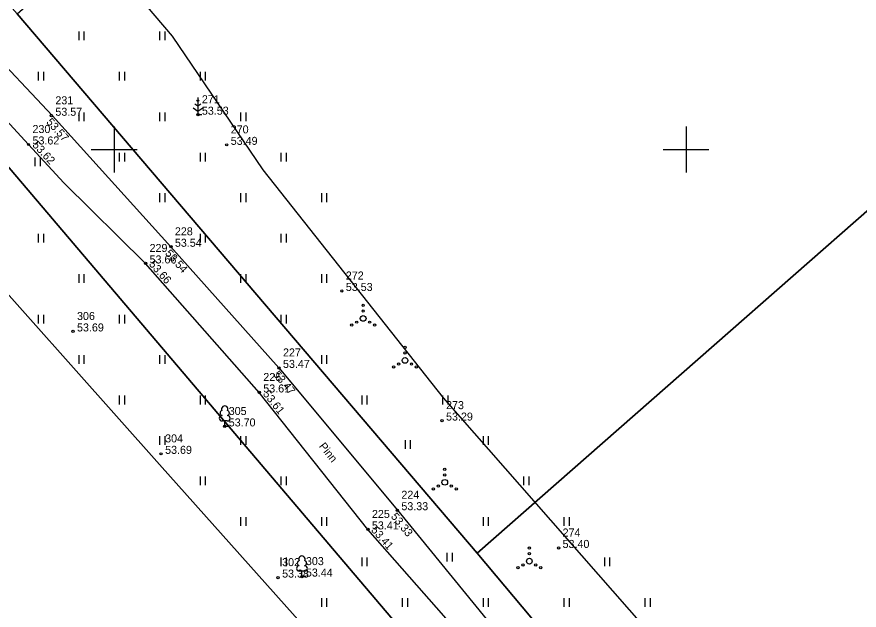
# Model space of a CAD drawing. Extents: x 538599 to 541973, y 6559689 to 6564516.
# Drawn here: x 540391.5 to 540465.1, y 6561409.8 to 6561461.6 of the extents above; entities that cross this region are included whole.
import ezdxf

# ---------------------------------------------------------------- set-up
doc = ezdxf.new("R2010")
doc.units = 0
for name, color, linetype in [('HALJASTUS', 7, 'Continuous'), ('KORGUS-EH2000', 7, 'Continuous'), ('MOOTKORG-EH2000', 7, 'Continuous'), ('MOOTMPUNKT', 7, 'Continuous'), ('MOOTNR', 7, 'Continuous'), ('MOOTPIIR', 7, 'Continuous'), ('PIIR', 7, 'Continuous'), ('PUU', 7, 'Continuous'), ('TEE', 7, 'Continuous'), ('VORK', 7, 'Continuous')]:
    doc.layers.add(name, color=color, linetype=linetype)

msp = doc.modelspace()

# ---------------------------------------------------------------- linework, layer by layer
at = {"layer": 'HALJASTUS'}
for p, q in [((540396.9, 6561460.313), (540396.9, 6561459.552)), ((540397.355, 6561460.313), (540397.355, 6561459.552)), ((540403.971, 6561460.313), (540403.971, 6561459.552)), ((540404.426, 6561460.313), (540404.426, 6561459.552)), ((540393.364, 6561456.777), (540393.364, 6561456.016)), ((540393.819, 6561456.777), (540393.819, 6561456.016)), ((540400.435, 6561456.777), (540400.435, 6561456.016)), ((540400.89, 6561456.777), (540400.89, 6561456.016)), ((540407.506, 6561456.777), (540407.506, 6561456.016)), ((540407.961, 6561456.777), (540407.961, 6561456.016)), ((540396.9, 6561453.242), (540396.9, 6561452.48)), ((540397.355, 6561453.242), (540397.355, 6561452.48)), ((540403.971, 6561453.242), (540403.971, 6561452.48)), ((540404.426, 6561453.242), (540404.426, 6561452.48)), ((540411.042, 6561453.242), (540411.042, 6561452.48)), ((540411.497, 6561453.242), (540411.497, 6561452.48)), ((540393.061, 6561449.311), (540393.061, 6561448.55)), ((540393.516, 6561449.311), (540393.516, 6561448.55)), ((540400.435, 6561449.706), (540400.435, 6561448.945)), ((540400.89, 6561449.706), (540400.89, 6561448.945)), ((540407.506, 6561449.706), (540407.506, 6561448.945)), ((540407.961, 6561449.706), (540407.961, 6561448.945)), ((540414.577, 6561449.706), (540414.577, 6561448.945)), ((540415.032, 6561449.706), (540415.032, 6561448.945)), ((540403.971, 6561446.171), (540403.971, 6561445.409)), ((540404.426, 6561446.171), (540404.426, 6561445.409)), ((540411.042, 6561446.171), (540411.042, 6561445.409)), ((540411.497, 6561446.171), (540411.497, 6561445.409)), ((540418.113, 6561446.171), (540418.113, 6561445.409)), ((540418.568, 6561446.171), (540418.568, 6561445.409)), ((540393.364, 6561442.635), (540393.364, 6561441.874)), ((540393.819, 6561442.635), (540393.819, 6561441.874)), ((540407.506, 6561442.635), (540407.506, 6561441.874)), ((540407.961, 6561442.635), (540407.961, 6561441.874)), ((540414.577, 6561442.635), (540414.577, 6561441.874)), ((540415.032, 6561442.635), (540415.032, 6561441.874)), ((540396.9, 6561439.099), (540396.9, 6561438.338)), ((540397.355, 6561439.099), (540397.355, 6561438.338)), ((540411.042, 6561439.099), (540411.042, 6561438.338)), ((540411.497, 6561439.099), (540411.497, 6561438.338)), ((540418.113, 6561439.099), (540418.113, 6561438.338)), ((540418.568, 6561439.099), (540418.568, 6561438.338)), ((540393.364, 6561435.564), (540393.364, 6561434.803)), ((540393.819, 6561435.564), (540393.819, 6561434.803)), ((540400.435, 6561435.564), (540400.435, 6561434.803)), ((540400.89, 6561435.564), (540400.89, 6561434.803)), ((540414.577, 6561435.564), (540414.577, 6561434.803)), ((540415.032, 6561435.564), (540415.032, 6561434.803)), ((540396.9, 6561432.028), (540396.9, 6561431.267)), ((540397.355, 6561432.028), (540397.355, 6561431.267)), ((540403.971, 6561432.028), (540403.971, 6561431.267)), ((540404.426, 6561432.028), (540404.426, 6561431.267)), ((540418.113, 6561432.028), (540418.113, 6561431.267)), ((540418.568, 6561432.028), (540418.568, 6561431.267)), ((540400.435, 6561428.493), (540400.435, 6561427.732)), ((540400.89, 6561428.493), (540400.89, 6561427.732)), ((540407.506, 6561428.493), (540407.506, 6561427.732)), ((540407.961, 6561428.493), (540407.961, 6561427.732)), ((540421.648, 6561428.493), (540421.648, 6561427.732)), ((540422.103, 6561428.493), (540422.103, 6561427.732)), ((540428.719, 6561428.493), (540428.719, 6561427.732)), ((540429.175, 6561428.493), (540429.175, 6561427.732)), ((540403.971, 6561424.957), (540403.971, 6561424.196)), ((540404.426, 6561424.957), (540404.426, 6561424.196)), ((540411.042, 6561424.957), (540411.042, 6561424.196)), ((540411.497, 6561424.957), (540411.497, 6561424.196)), ((540432.255, 6561424.957), (540432.255, 6561424.196)), ((540432.71, 6561424.957), (540432.71, 6561424.196)), ((540425.436, 6561424.598), (540425.436, 6561423.836)), ((540425.891, 6561424.598), (540425.891, 6561423.836)), ((540407.506, 6561421.422), (540407.506, 6561420.661)), ((540407.961, 6561421.422), (540407.961, 6561420.661)), ((540414.577, 6561421.422), (540414.577, 6561420.661)), ((540415.032, 6561421.422), (540415.032, 6561420.661)), ((540435.791, 6561421.422), (540435.791, 6561420.661)), ((540436.246, 6561421.422), (540436.246, 6561420.661)), ((540411.042, 6561417.886), (540411.042, 6561417.125)), ((540411.497, 6561417.886), (540411.497, 6561417.125)), ((540418.113, 6561417.886), (540418.113, 6561417.125)), ((540418.568, 6561417.886), (540418.568, 6561417.125)), ((540432.255, 6561417.886), (540432.255, 6561417.125)), ((540432.71, 6561417.886), (540432.71, 6561417.125)), ((540439.326, 6561417.886), (540439.326, 6561417.125)), ((540439.781, 6561417.886), (540439.781, 6561417.125)), ((540429.096, 6561414.775), (540429.096, 6561414.014)), ((540429.551, 6561414.775), (540429.551, 6561414.014)), ((540414.577, 6561414.351), (540414.577, 6561413.59)), ((540415.032, 6561414.351), (540415.032, 6561413.59)), ((540421.648, 6561414.351), (540421.648, 6561413.59)), ((540422.103, 6561414.351), (540422.103, 6561413.59)), ((540442.862, 6561414.351), (540442.862, 6561413.59)), ((540443.317, 6561414.351), (540443.317, 6561413.59)), ((540418.113, 6561410.815), (540418.113, 6561410.054)), ((540418.568, 6561410.815), (540418.568, 6561410.054)), ((540425.184, 6561410.815), (540425.184, 6561410.054)), ((540425.639, 6561410.815), (540425.639, 6561410.054)), ((540432.255, 6561410.815), (540432.255, 6561410.054)), ((540432.71, 6561410.815), (540432.71, 6561410.054)), ((540439.326, 6561410.815), (540439.326, 6561410.054)), ((540439.781, 6561410.815), (540439.781, 6561410.054)), ((540446.397, 6561410.815), (540446.397, 6561410.054)), ((540446.852, 6561410.815), (540446.852, 6561410.054))]:
    msp.add_line(p, q, dxfattribs=at)
for centre, radius in [((540421.77, 6561436.387), 0.1), ((540421.77, 6561435.887), 0.1), ((540421.77, 6561435.237), 0.25), ((540420.77, 6561434.662), 0.1), ((540421.205, 6561434.912), 0.1), ((540422.335, 6561434.912), 0.1), ((540422.77, 6561434.662), 0.1), ((540425.43, 6561432.726), 0.1), ((540425.43, 6561432.226), 0.1), ((540425.43, 6561431.576), 0.25), ((540424.43, 6561431.001), 0.1), ((540424.865, 6561431.251), 0.1), ((540425.995, 6561431.251), 0.1), ((540426.43, 6561431.001), 0.1), ((540428.908, 6561422.07), 0.1), ((540428.908, 6561420.92), 0.25), ((540428.908, 6561421.57), 0.1), ((540427.908, 6561420.345), 0.1), ((540428.343, 6561420.595), 0.1), ((540429.473, 6561420.595), 0.1), ((540429.908, 6561420.345), 0.1), ((540436.3, 6561415.183), 0.1), ((540436.3, 6561414.683), 0.1), ((540435.735, 6561413.708), 0.1), ((540436.3, 6561414.033), 0.25), ((540436.865, 6561413.708), 0.1), ((540435.3, 6561413.458), 0.1), ((540437.3, 6561413.458), 0.1)]:
    msp.add_circle(centre, radius, dxfattribs=at)
at = {"layer": 'KORGUS-EH2000'}
for centre in [(540394.506, 6561452.944), (540392.506, 6561450.435), (540409.841, 6561450.403), (540404.957, 6561441.5), (540402.743, 6561440.044), (540419.903, 6561437.639), (540396.4, 6561434.103), (540414.409, 6561430.917), (540412.686, 6561428.773), (540428.668, 6561426.316), (540404.103, 6561423.41), (540424.761, 6561418.487), (540422.187, 6561416.809), (540438.858, 6561415.19), (540414.334, 6561412.601)]:
    msp.add_circle(centre, 0.1, dxfattribs=at)
at = {"layer": 'MOOTMPUNKT'}
for centre in [(540394.506, 6561452.944), (540407.317, 6561453.036), (540392.506, 6561450.435), (540409.841, 6561450.403), (540404.957, 6561441.5), (540402.743, 6561440.044), (540419.903, 6561437.639), (540396.4, 6561434.103), (540414.409, 6561430.917), (540412.686, 6561428.773), (540428.668, 6561426.316), (540409.666, 6561425.805), (540404.103, 6561423.41), (540424.761, 6561418.487), (540422.187, 6561416.809), (540438.858, 6561415.19), (540414.334, 6561412.601), (540416.414, 6561412.691)]:
    msp.add_circle(centre, 0.1, dxfattribs=at)
at = {"layer": 'MOOTPIIR'}
for points in [[(540611.814, 6561347.628), (540600.551, 6561344.045), (540588.991, 6561338.307), (540579.507, 6561329.749), (540567.369, 6561324.711), (540557.296, 6561315.504), (540537.549, 6561303.29), (540525.23, 6561316.048), (540500.22, 6561345.282), (540476.488, 6561371.995), (540449.028, 6561405.277), (540428.792, 6561428.292), (540413.022, 6561448.218), (540405.096, 6561459.889), (540393.809, 6561473.145)], [(540384.887, 6561443.845), (540403.973, 6561422.469), (540424.304, 6561399.698), (540444.636, 6561376.927), (540453.177, 6561363.987), (540470.995, 6561343.689), (540492.689, 6561318.976), (540511.766, 6561294.341), (540521.974, 6561279.181), (540525.589, 6561267.954), (540536.495, 6561252.794), (540542.772, 6561231.926), (540526.603, 6561219.05), (540510.624, 6561213.468), (540498.26, 6561199.196), (540484.564, 6561192.98), (540479.618, 6561185.622), (540478.413, 6561178.328), (540490.461, 6561165.832), (540493.58, 6561162.597), (540531.105, 6561187.906), (540582.869, 6561222.817), (540621.742, 6561247.747)]]:
    msp.add_lwpolyline(points, dxfattribs=at)
at = {"layer": 'PIIR'}
for points in [[(540491.21, 6561183.5), (540566.07, 6561233.36), (540528.84, 6561281.85), (540494.34, 6561324.62), (540458.27, 6561368.69), (540424.68, 6561408.57), (540384.55, 6561455.73), (540346.17, 6561499.11), (540330.12, 6561517.14), (540337.36, 6561523.32), (540348.28, 6561532.96), (540364.11, 6561514.94), (540353.14, 6561505.27), (540391.51, 6561461.86), (540431.74, 6561414.74), (540465.17, 6561374.89), (540501.31, 6561330.86), (540535.92, 6561287.97), (540573.77, 6561238.75), (540640.63, 6561283.66), (540646.74, 6561272.89), (540499, 6561174.36)], [(540391.51, 6561461.86), (540460.86, 6561522.64), (540500.82, 6561475.34), (540431.74, 6561414.74)], [(540431.74, 6561414.74), (540500.82, 6561475.34), (540537.11, 6561431.06), (540465.17, 6561374.89)], [(540309.49, 6561390.29), (540384.55, 6561455.73), (540424.68, 6561408.57), (540350.66, 6561343.77)]]:
    msp.add_lwpolyline(points, close=True, dxfattribs=at)
at = {"layer": 'PUU'}
for p, q in [((540407.317, 6561454.186), (540407.193, 6561454.269)), ((540407.317, 6561454.536), (540407.317, 6561453.036)), ((540407.441, 6561454.269), (540407.317, 6561454.186)), ((540406.893, 6561453.625), (540407.317, 6561453.343)), ((540407.317, 6561453.786), (540407.05, 6561453.964)), ((540407.584, 6561453.964), (540407.317, 6561453.786)), ((540407.317, 6561453.343), (540407.741, 6561453.625)), ((540407.677, 6561453.036), (540407.317, 6561453.036)), ((540409.906, 6561426.28), (540409.426, 6561426.28)), ((540409.666, 6561425.805), (540409.666, 6561426.28)), ((540410.046, 6561425.805), (540409.666, 6561425.805)), ((540416.654, 6561413.166), (540416.174, 6561413.166)), ((540416.414, 6561412.691), (540416.414, 6561413.166)), ((540416.794, 6561412.691), (540416.414, 6561412.691))]:
    msp.add_line(p, q, dxfattribs=at)
for centre, radius, start, end in [((540409.496, 6561426.978), 0.233, 109.02174, 253.14154), ((540409.666, 6561427.325), 0.277, 332.5799, 207.4201), ((540409.836, 6561426.978), 0.233, 286.85082, 70.98591), ((540409.429, 6561426.517), 0.238, 90.0016, 269.3953), ((540409.903, 6561426.517), 0.238, 270.6047, 89.9984), ((540416.414, 6561414.211), 0.277, 332.5799, 207.4201), ((540416.244, 6561413.864), 0.233, 109.02174, 253.14154), ((540416.584, 6561413.864), 0.233, 286.85082, 70.98591), ((540416.177, 6561413.403), 0.238, 90.0016, 269.3953), ((540416.651, 6561413.403), 0.238, 270.6047, 89.9984)]:
    msp.add_arc(centre, radius, start, end, dxfattribs=at)
at = {"layer": 'TEE'}
for points in [[(540488.154, 6561336.579), (540478.587, 6561348.431), (540467.854, 6561361.491), (540459.324, 6561371.761), (540451.227, 6561381.751), (540441.058, 6561393.627), (540438.742, 6561396.541), (540432.536, 6561404.858), (540428.826, 6561409.256), (540422.187, 6561416.809), (540412.686, 6561428.773), (540402.743, 6561440.044), (540395.606, 6561447.094), (540392.506, 6561450.435), (540382.51, 6561461.307)], [(540388.6, 6561459.282), (540394.606, 6561452.944), (540404.957, 6561441.5), (540414.409, 6561430.917), (540424.761, 6561418.487), (540434.319, 6561406.773), (540435.946, 6561404.714), (540443.752, 6561395.534), (540453.227, 6561383.82), (540461.243, 6561373.674), (540469.957, 6561362.956), (540476.197, 6561354.987), (540480.237, 6561350.173), (540490.343, 6561338.333)]]:
    msp.add_lwpolyline(points, dxfattribs=at)
at = {"layer": 'VORK'}
for p, q in [((540400, 6561452), (540400, 6561448)), ((540450, 6561452), (540450, 6561448)), ((540398, 6561450), (540402, 6561450)), ((540448, 6561450), (540452, 6561450))]:
    msp.add_line(p, q, dxfattribs=at)

# ---------------------------------------------------------------- texts
at = {"layer": 'KORGUS-EH2000'}
for s, rotation, p in [('53.57', 312.12907, (540394.01, 6561452.357)), ('53.62', 312.84976, (540392.798, 6561450.346)), ('53.54', 311.76901, (540404.403, 6561440.886)), ('53.66', 311.41795, (540402.993, 6561439.947)), ('53.47', 309.78834, (540413.867, 6561430.308)), ('53.61', 308.45423, (540412.962, 6561428.624)), ('53.33', 309.21261, (540424.151, 6561417.919)), ('53.41', 311.31429, (540422.415, 6561416.721))]:
    msp.add_text(s, height=0.7, rotation=rotation, dxfattribs=at).set_placement(p)
for s, p in [('53.49', (540410.191, 6561450.403)), ('53.53', (540420.253, 6561437.639)), ('53.69', (540396.75, 6561434.103)), ('53.29', (540429.018, 6561426.316)), ('53.69', (540404.453, 6561423.41)), ('53.40', (540439.208, 6561415.19)), ('53.38', (540414.684, 6561412.601))]:
    msp.add_text(s, height=0.7, dxfattribs=at).set_placement(p)
at = {"layer": 'MOOTKORG-EH2000'}
for s, p in [('53.57', (540394.856, 6561452.944)), ('53.53', (540407.667, 6561453.036)), ('53.62', (540392.856, 6561450.435)), ('53.49', (540410.191, 6561450.403)), ('53.54', (540405.307, 6561441.5)), ('53.66', (540403.093, 6561440.044)), ('53.53', (540420.253, 6561437.639)), ('53.69', (540396.75, 6561434.103)), ('53.47', (540414.759, 6561430.917)), ('53.61', (540413.036, 6561428.773)), ('53.29', (540429.018, 6561426.316)), ('53.70', (540410.016, 6561425.805)), ('53.69', (540404.453, 6561423.41)), ('53.33', (540425.111, 6561418.487)), ('53.41', (540422.537, 6561416.809)), ('53.40', (540439.208, 6561415.19)), ('53.38', (540414.684, 6561412.601)), ('53.44', (540416.764, 6561412.691))]:
    msp.add_text(s, height=0.7, dxfattribs=at).set_placement(p)
at = {"layer": 'MOOTNR'}
for s, p in [('231', (540394.856, 6561453.944)), ('271', (540407.667, 6561454.036)), ('230', (540392.856, 6561451.435)), ('270', (540410.191, 6561451.403)), ('228', (540405.307, 6561442.5)), ('229', (540403.093, 6561441.044)), ('272', (540420.253, 6561438.639)), ('306', (540396.75, 6561435.103)), ('227', (540414.759, 6561431.917)), ('226', (540413.036, 6561429.773)), ('273', (540429.018, 6561427.316)), ('305', (540410.016, 6561426.805)), ('304', (540404.453, 6561424.41)), ('224', (540425.111, 6561419.487)), ('225', (540422.537, 6561417.809)), ('274', (540439.208, 6561416.19)), ('302', (540414.684, 6561413.601)), ('303', (540416.764, 6561413.691))]:
    msp.add_text(s, height=0.7, dxfattribs=at).set_placement(p)
at = {"layer": 'TEE'}
msp.add_text('Pinn', height=0.7, rotation=308.45423, dxfattribs=at).set_placement((540417.869, 6561424.063))

doc.saveas('drawing.dxf')
